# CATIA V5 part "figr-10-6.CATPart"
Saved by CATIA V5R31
Part number: Part1
Bounding box of the stored display mesh (mm): x -9.888 to 10, y -9.972 to 9.972, z 0 to 10
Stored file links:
  D:\PROJECTS\Project 2021\US EDITION\CATIA V5 6R 2021\Resources\Part Files\c10_catia_v5_6r2021_prt\c10_catia_v5_6r2021_prt\figr-10-6.CATPart
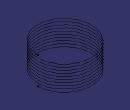
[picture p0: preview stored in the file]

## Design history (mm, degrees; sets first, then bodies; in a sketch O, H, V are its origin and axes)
Set1
  Helix1: Direction {line stored without definition}, RefPoint {point type Coord, X 10, Y 0, Z 0}, Pitch 1, Height 10, TaperAngle 0
Body1 (main body)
